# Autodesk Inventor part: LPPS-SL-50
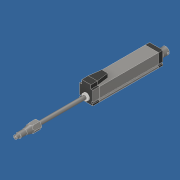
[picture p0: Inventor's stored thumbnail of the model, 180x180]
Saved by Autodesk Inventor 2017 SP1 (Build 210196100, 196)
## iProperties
Created: 2016-12
Part Number: LPPS-SL-50
Material: Stainless Steel
Document SubType Name: Modeling
Designer: JN
Density: 8 g/cm^3
Appearance: Stainless - Brushed
Author: JN
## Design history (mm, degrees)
sketch "Sketch1"
  geometry: C1 r 2.54 at (0, 0)
  constraints: 1 centre point, 1 other
  dimensions: "d0" = 5.08 diameter of C1
extrude "Extrusion1" new body sketch "Sketch1" distance "d1" = 4.572; taper "d2" = 0 deg
sketch "Sketch2"
  geometry: C1 r 3.48 at (0, 0)
  constraints: 1 centre point
  dimensions: "d3" = 6.9596 diameter of C1
extrude "Extrusion2" join sketch "Sketch2" distance "d4" = 8.2042; taper "d5" = 0 deg
workaxis "Work Axis1"
revolve "Revolution2" stored, may be unused: angle "d8" = 90 deg
sketch "Sketch7"
  geometry: L1 (-5.778, 0)-(-2.889, 5.004); L2 (-2.889, 5.004)-(2.889, 5.004); L3 (2.889, 5.004)-(5.778, 0); L4 (5.778, 0)-(2.889, -5.004); L5 (2.889, -5.004)-(-2.889, -5.004); L6 (-2.889, -5.004)-(-5.778, 0); L7 (0, 0)-(0, 8.469); L8 (-0.303, -0.272)-(8.166, -0.272); L9 (0, -3.48)-(0, 0)
  constraints: 18 end point, 3 perpendicular, 1 horizontal, 1 vertical alignment, 14 other
  dimensions: "d20" = 90 deg angle of L8 L7; "d23" = 10.0076 distance between parallel lines of L5 L2
extrude "Extrusion4" join sketch "Sketch7" distance "d21" = 18.03974; taper "d22" = 0 deg
sketch "Sketch8"
  geometry: L1 (3.48, -4.572)-(3.48, -12.776) reference; L2 (0, 1.416)-(0, -21.685); L3 (0, -12.776)-(0, -30.816) reference; L4 (0, 9.356)-(0, -46.226) reference; L5 (5.004, -30.816)-(-5.004, -30.816); L6 (5.004, -30.816)-(0, -30.816) reference; L7 (0, -30.816)-(-5.004, -30.816) reference; L8 (-5.004, -12.776)-(-5.004, -30.816) reference; L9 (-5.004, -30.816)-(-5.004, -12.776); L10 (4.859, -30.943)-(-0.272, -30.943); L11 (-3.48, -12.776)-(3.48, -12.776) reference; L12 (3.48, -4.572)-(3.48, -12.776) reference; L13 (3.48, -12.776)-(3.481, -12.776); L14 (3.481, -12.776)-(9.456, -38.286); L15 (3.481, -12.776)-(9.456, -12.776); L16 (9.456, -38.286)-(9.456, -12.776); A1 r 1.416 centre (0, 0) between (1.416, 0) and (-1.416, 0) reference; 1 further point
  constraints: 16 end point, 2 collinear, 1 horizontal, 1 perpendicular, 1 point on circle, 1 point on line, 1 vertical
revolve "Revolution9" sketch "Sketch8" stored, may be unused: angle "d35" = 90 deg
sketch "Sketch9"
  geometry: C1 r 2.54 at (0, 0)
  constraints: 1 centre point
  dimensions: "d36" = 5.08 diameter of C1
extrude "Extrusion5" join sketch "Sketch9" distance "d37" = 64.77 (= Stroke); taper "d38" = 0 deg
sketch "Sketch10"
  geometry: C1 r 2.54 at (0, 0) reference; C2 r 4.521 at (0, 0)
  constraints: 1 centre point, 1 coincident
  dimensions: "d39" = 9.0424 diameter of C2
extrude "Extrusion6" join sketch "Sketch10" distance "d40" = 2; taper "d41" = 0 deg
sketch "Sketch11"
  geometry: L1 (-9.143, 16.927)-(9.145, 16.927); L2 (9.145, -6.949)-(-9.143, -6.949); L3 (-9.143, -6.949)-(-9.143, 16.927); L4 (-5.778, 0)-(-2.889, -5.004) reference; L5 (5.778, 0)-(2.889, 5.004) reference; L6 (-5.778, 0)-(5.778, 0); L7 (2.889, 5.004)-(-2.889, 5.004) reference; L8 (0, 5.004)-(0, -5.004); L9 (-2.889, -5.004)-(2.889, -5.004) reference; L10 (9.145, -6.949)-(9.145, -4.663); L11 (9.145, -4.663)-(7.621, -4.663); L12 (7.621, -4.663)-(7.621, -2.377); L13 (7.621, -2.377)-(9.145, -2.377); L14 (9.145, 16.927)-(9.145, -2.377); L15 (9.145, -4.663)-(9.145, -6.949); L16 (-9.143, -2.377)-(-7.619, -2.377); L17 (-7.619, -2.377)-(-7.619, -4.663); L18 (-7.619, -4.663)-(-9.143, -4.663)
  constraints: 28 end point, 9 perpendicular, 4 parallel, 4 point on line, 2 horizontal, 2 midpoint
  dimensions: "d42" = 18.288 distance of L1.start L1.end; "d43" = 3.3655 distance from line of L3 L4.start; "d47" = 23.876 distance of L1.end L2.start; "d49" = 1.94564 distance between parallel lines of L2 L9; "d98" = 2.286 distance of L2.start L10.end; "d99" = 1.524 distance of L10.end L11.end; "d100" = 2.286 distance of L11.end L12.end; "d101" = 1.524 distance of L16.start L16.end
extrude "Extrusion7" join sketch "Sketch11" distance "d50" = 9; taper "d51" = 0 deg
sketch "Sketch12"
  geometry: L1 (-9.145, -6.949)-(-9.145, 16.927) reference; L2 (9.143, 16.927)-(9.143, -6.949) reference; L3 (9.143, -6.949)-(-9.145, -6.949) reference; L4 (-9.145, -6.949)-(9.143, -6.949); L5 (-9.145, 16.927)-(9.143, 16.927); L6 (-9.145, 16.927)-(-9.145, -6.949); L7 (-9.145, 16.927)-(9.143, 16.927) reference; L8 (-6.319, 16.927)-(-6.319, 11.593); L9 (6.318, 16.927)-(6.318, 11.593); L10 (-9.145, 11.593)-(-6.319, 11.593); L11 (6.318, 11.593)-(9.143, 11.593)
  constraints: 15 end point, 4 parallel, 2 perpendicular, 2 point on line, 1 collinear
  dimensions: "d52" = 23.876 distance between parallel lines of L4 L5; "d55" = 2.82575 distance between parallel lines of L8 L1; "d56" = 2.82575 distance between parallel lines of L9 L2; "d57" = 18.542 distance between parallel lines of L3 L10; "d58" = 18.542 distance between parallel lines of L3 L11
extrude "Extrusion8" cut sketch "Sketch12" distance "d59" = 9; taper "d60" = 0 deg
mirror "Mirror1"
sketch "Sketch13"
  geometry: L1 (9.145, 11.593)-(6.319, 11.593) reference; L2 (-6.319, 16.927)-(6.319, 16.927); L3 (6.319, 16.927)-(6.319, 11.593); L4 (6.319, 11.593)-(-6.319, 11.593); L5 (-6.319, 11.593)-(-6.319, 16.927)
  constraints: 8 end point, 2 parallel, 1 horizontal, 1 perpendicular
workplane "Work Plane1"
sketch "Sketch14"
  geometry: L1 (6.319, 16.927)-(-6.319, 16.927) reference; L2 (-4.109, 16.927)-(4.121, 16.927); L3 (4.121, 16.927)-(4.121, 11.558); L4 (4.121, 11.558)-(-4.109, 11.558); L5 (-4.109, 11.558)-(-4.109, 16.927); L6 (-6.319, 16.927)-(-6.319, 11.593) reference; L7 (6.319, 11.593)-(6.319, 16.927) reference; 1 further point
  constraints: 8 end point, 2 parallel, 2 perpendicular, 1 horizontal, 1 point on line
  dimensions: "d62" = 8.2296 distance of L3.end L4.end; "d63" = 2.2098 distance between parallel lines of L6 L5; "d65" = 2.6844 distance from line of point (0.006, 14.242) L1; "d66" = 4.1148 distance from line of L5 point (0.006, 14.242)
sketch "3D Sketch1"
loft "Loft1" sketch "3D Sketch1" dims "d67" = 0, "d68" = 90 deg, "d69" = 0, "d70" = 90 deg, "d71" = 0, "d72" = 90 deg
sketch "Sketch15"
  geometry: L1 (-6.319, 11.593)-(-9.143, 11.593) reference; L2 (9.145, -6.949)-(9.145, 11.593) reference; L3 (-9.143, 11.593)-(9.145, 11.593); L4 (9.145, -6.949)-(-9.143, -6.949); L5 (7.621, -2.377)-(9.145, -2.377) reference; L6 (9.145, -2.377)-(7.621, -2.377); L7 (7.621, -4.663)-(7.621, -2.377) reference; L8 (7.621, -2.377)-(7.621, -4.663); L9 (9.145, -4.663)-(7.621, -4.663) reference; L10 (7.621, -4.663)-(9.145, -4.663); L11 (-9.143, -2.377)-(-7.619, -2.377) reference; L12 (-7.619, -4.663)-(-9.143, -4.663) reference; L13 (-9.143, -4.663)-(-7.619, -4.663); L14 (-7.619, -2.377)-(-7.619, -4.663) reference; L15 (-7.619, -4.663)-(-7.619, -2.377); L16 (-9.143, 11.593)-(-9.143, -2.377) reference; L17 (-7.619, -2.377)-(-9.143, -2.377); L18 (9.145, 11.593)-(9.145, -2.377); L19 (9.145, -4.663)-(9.145, -6.949); L20 (-9.143, -6.949)-(-9.143, -4.663); L21 (-9.143, -2.377)-(-9.143, 11.593)
  constraints: 24 end point, 5 parallel, 5 perpendicular, 3 collinear, 1 horizontal
extrude "Extrusion9" new body sketch "Sketch15" distance "d73" = 81.0514 (= Body); taper "d74" = 0 deg
sketch "Sketch16"
  geometry: L1 (-9.143, 11.593)-(-9.143, -6.949) reference; L2 (-9.143, -6.949)-(9.145, -6.949) reference; L3 (-9.143, 11.593)-(9.145, 11.593); L4 (9.145, -6.949)-(-9.143, -6.949); L5 (7.621, -2.377)-(9.145, -2.377) reference; L6 (9.145, -2.377)-(7.621, -2.377); L7 (9.145, -4.663)-(7.621, -4.663) reference; L8 (7.621, -2.377)-(7.621, -4.663); L9 (7.621, -4.663)-(9.145, -4.663); L10 (-9.143, -2.377)-(-7.619, -2.377) reference; L11 (-9.143, -2.377)-(-7.619, -2.377); L12 (-7.619, -2.377)-(-7.619, -4.663) reference; L13 (-7.619, -2.377)-(-7.619, -4.663); L14 (-7.619, -4.663)-(-9.143, -4.663) reference; L15 (-7.619, -4.663)-(-9.143, -4.663); L16 (-9.143, -6.949)-(-9.143, -4.663); L17 (-9.143, -2.377)-(-9.143, 11.593); L18 (9.145, 11.593)-(9.145, -2.377); L19 (9.145, -4.663)-(9.145, -6.949)
  constraints: 24 end point, 5 parallel, 4 perpendicular, 3 collinear, 2 horizontal
extrude "Extrusion10" new body sketch "Sketch16" distance "d75" = 6.0071; taper "d76" = 0 deg
sketch "Sketch17"
  geometry: L1 (-9.143, 11.593)-(9.145, 11.593) reference; L2 (9.145, 11.593)-(9.145, -2.377) reference; L3 (9.145, -6.949)-(-9.143, -6.949) reference; L4 (-9.143, -6.949)-(-9.143, -4.663) reference; L5 (-9.143, -4.663)-(-7.619, -4.663) reference; L6 (-7.619, -4.663)-(-7.619, -2.377) reference; L7 (-7.619, -2.377)-(-9.143, -2.377) reference; L8 (-9.143, -2.377)-(-9.143, 11.593) reference; L9 (9.145, -2.377)-(7.621, -2.377) reference; L10 (7.621, -2.377)-(7.621, -4.663) reference; L11 (7.621, -4.663)-(9.145, -4.663) reference; L12 (9.145, -4.663)-(9.145, -6.949) reference; C1 r 2.54 at (0, 0) reference; C2 r 1.416 at (0, 0) reference; C3 r 4.051 at (0, 0)
  constraints: 1 centre point, 1 coincident
  dimensions: "d77" = 8.1026 diameter of C3
extrude "Extrusion11" new body sketch "Sketch17" distance "d78" = 5; taper "d79" = 0 deg
sketch "Sketch18"
  geometry: C1 r 1.416 at (0, 0) reference; C2 r 5 at (0, 0)
  constraints: 1 centre point, 1 coincident
  dimensions: "d80" = 10 diameter of C2
extrude "Extrusion12" new body sketch "Sketch18" distance "d81" = 8; taper "d82" = 0 deg
shell "Shell2" dims "d84" = 1.397
workaxis "Work Axis4"
workplane "Work Plane2"
sketch "Sketch19"
  geometry: L1 (-5, -8)-(5, -8) reference; L2 (0, -8)-(0, -6.095); 1 further point
  constraints: 2 end point, 1 coincident, 1 midpoint, 1 vertical
  dimensions: "d85" = 1.905 distance of L2.start L2.end
hole "Hole1" sketch "Sketch19" at (0, -6.095) diameter "d86" = 2.3876; stored, may be unused: countersink angle "d90" = 82 deg, drill point angle "d92" = 118 deg; dims "d87" = 19.05, "d88" = 9.525, "d89" = 6.35, "d91" = 25.4
body "Solid1"
sketch "Sketch3"
  geometry: L1 (-2.54, 0)-(2.54, 0) reference; L2 (1.416, 0)-(0, 0); L3 (0, 0)-(0, 1.416); A1 r 1.416 centre (0, 0) between (1.416, 0) and (0, 1.416)
  constraints: 4 end point, 2 point on circle, 1 centre point, 1 midpoint, 1 vertical
  dimensions: "d6" = 2.8321 diameter of A1
body "Solid2"
body "Solid3"
body "Solid4"
body "Solid5"
node "Project Cut Edges1"
other parameters: "Stroke" = 64.77 [user parameter; used in 1 equation term], "Body" = 81.0514 [user parameter; used in 1 equation term], "d53" = 5.334, "d61" = 16.51
